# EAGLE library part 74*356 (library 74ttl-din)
8-to 1 line data SELECTOR/MULTIPLEXER/REGISTER, 3-state
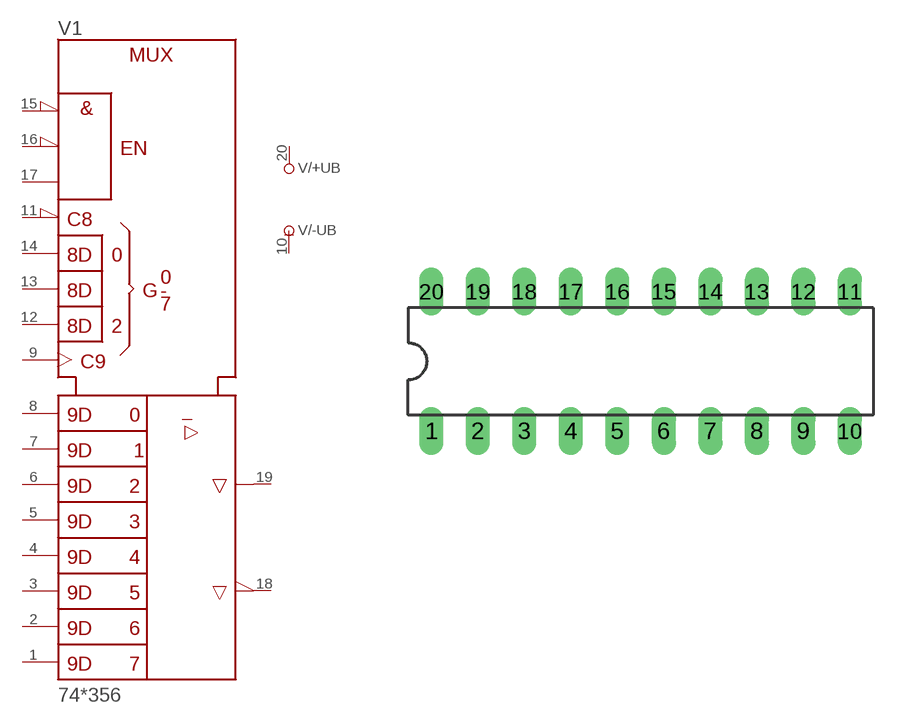
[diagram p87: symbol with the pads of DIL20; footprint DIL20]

Designator prefix V; gates /+UB=+UB /-UB=-UB 1=356

## 74356N  [DIL20]
1  1:D7  in
2  1:D6  in
3  1:D5  in
4  1:D4  in
5  1:D3  in
6  1:D2  in
7  1:D1  in
8  1:D0  in
9  1:CLK  in
10  /-UB:-UB  pwr
11  1:SC\  in
12  1:S2  in
13  1:S1  in
14  1:S0  in
15  1:G\1  in
16  1:G\2  in
17  1:G3  in
18  1:W  hiz
19  1:Y  hiz
20  /+UB:+UB  pwr

## Footprint DIL20 (pad centres in mm)
Dual In Line Package
drill 0.813 long: 1 -11.43,-3.81; 2 -8.89,-3.81; 3 -6.35,-3.81; 4 -3.81,-3.81; 5 -1.27,-3.81; 6 1.27,-3.81; 7 3.81,-3.81; 8 6.35,-3.81; 9 8.89,-3.81; 10 11.43,-3.81; 11 11.43,3.81; 12 8.89,3.81; 13 6.35,3.81; 14 3.81,3.81; 15 1.27,3.81; 16 -1.27,3.81; 17 -3.81,3.81; 18 -6.35,3.81; 19 -8.89,3.81; 20 -11.43,3.81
